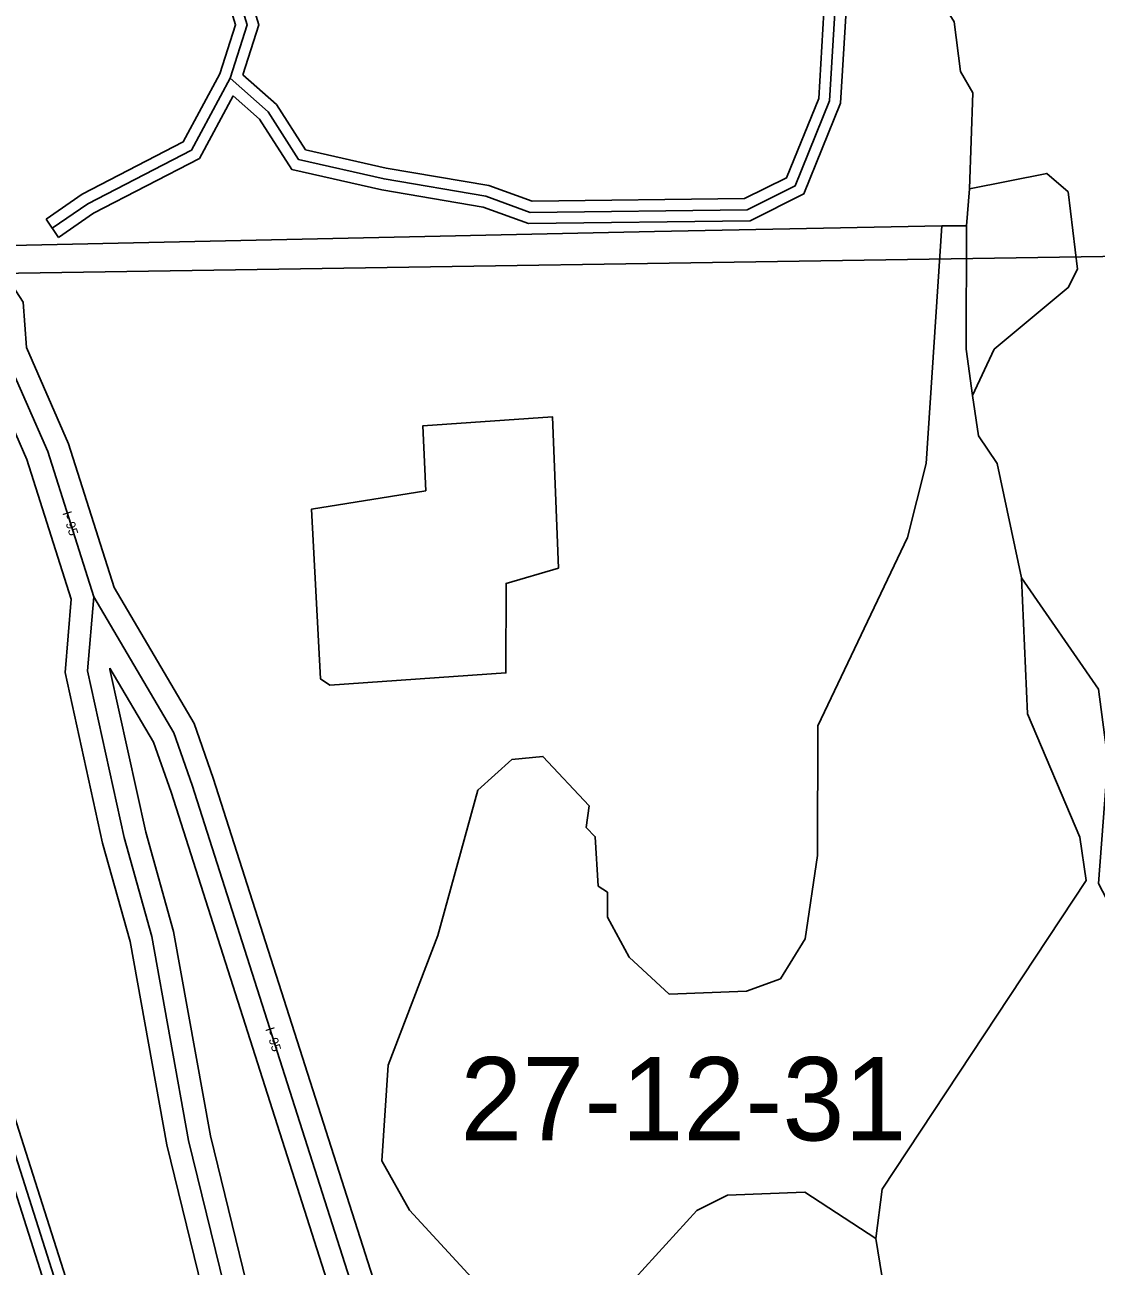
# Model space of a CAD drawing. Extents: x 457167 to 656239, y 1787309 to 1969297.
# Drawn here: x 602179 to 605072, y 1853646 to 1856997 of the extents above; entities that cross this region are included whole.
import ezdxf

# ---------------------------------------------------------------- set-up
doc = ezdxf.new("R2010")
doc.units = 0
for name, color, linetype in [('Level 1', 7, 'Continuous'), ('Level 13', 7, 'Continuous'), ('Level 14', 7, 'Continuous'), ('Level 2', 7, 'Continuous'), ('Level 31', 7, 'Continuous'), ('Level 32', 7, 'Continuous'), ('Level 34', 7, 'Continuous'), ('Level 5', 7, 'Continuous'), ('Level 7', 7, 'Continuous')]:
    doc.layers.add(name, color=color, linetype=linetype)

msp = doc.modelspace()

# ---------------------------------------------------------------- linework, layer by layer
at = {"layer": 'Level 1'}
msp.add_line((601829.454, 1856321.682), (605453.433, 1856377.391), dxfattribs=at)
at = {"layer": 'Level 13'}
for points in [[(602364.771, 1855452.871), (602240.559, 1855845.044), (602124.124, 1856111.754), (602116.017, 1856228.491), (602049.636, 1856328.95)], [(603435.562, 1851606.682), (603226.41, 1852058.606), (603210.01, 1852166.991), (603160.137, 1852242.334), (602778.426, 1853343.222), (602621.136, 1853985.256), (602521.973, 1854535.57), (602447.233, 1854802.582), (602347.93, 1855252.9), (602364.771, 1855452.871)], [(603251.367, 1853042.916), (603120.168, 1853459.458), (603070.344, 1853567.891), (602630.791, 1854944.132), (602581.018, 1855085.656), (602364.771, 1855452.871)]]:
    msp.add_lwpolyline(points, dxfattribs=at)
at = {"layer": 'Level 14'}
for points in [[(602419.92, 1855477.463), (602296.808, 1855866.164), (602183.262, 1856126.256), (602174.78, 1856248.397), (602104.315, 1856355.036)], [(602303.985, 1855446.073), (602184.31, 1855823.924), (602064.985, 1856097.252), (602057.254, 1856208.585), (601994.957, 1856302.861)], [(603308.596, 1853060.941), (603176.263, 1853481.082), (603126.39, 1853589.626), (602687.683, 1854963.217), (602635.683, 1855111.071), (602419.92, 1855477.463)], [(603381.11, 1851581.481), (603168.365, 1852041.17), (603152.667, 1852144.917), (603105.926, 1852215.526), (602720.817, 1853326.219), (602562.416, 1853972.785), (602463.427, 1854522.133), (602389, 1854788.024), (602287.377, 1855248.866), (602303.985, 1855446.073)], [(603490.015, 1851631.882), (603284.456, 1852076.043), (603267.355, 1852189.066), (603214.347, 1852269.141), (602836.036, 1853360.226), (602679.856, 1853997.726), (602580.519, 1854549.007), (602505.465, 1854817.14), (602408.483, 1855256.933), (602408.737, 1855259.966)], [(603194.138, 1853024.891), (603064.072, 1853437.835), (603014.298, 1853546.158), (602573.9, 1854925.048), (602526.354, 1855060.241), (602408.737, 1855259.965)]]:
    msp.add_lwpolyline(points, dxfattribs=at)
at = {"layer": 'Level 31'}
for points in [[(602733.165, 1856852.679), (602779.527, 1856996.973), (602702.537, 1857246.171), (602652.469, 1857401.876), (602675.284, 1857551.659), (602721.405, 1857751.589), (602752.911, 1857968.996)], [(604488.633, 1857314.916), (604391.432, 1857229.598), (604376.762, 1857209.256), (604351.99, 1856791.843), (604259.042, 1856562.522), (604129.719, 1856497.976)], [(602252.94, 1856447.746), (602348.798, 1856513.966), (602628.8, 1856658.651), (602733.165, 1856852.679)], [(604129.719, 1856497.976), (603543.7, 1856490.438), (603423.759, 1856534.243), (603148.805, 1856580.816), (602918.106, 1856633.145), (602835.849, 1856761.987), (602733.165, 1856852.679)], [(601862.03, 1854063.809), (602093.555, 1854131.834), (602486.724, 1852895.785)]]:
    msp.add_lwpolyline(points, dxfattribs=at)
at = {"layer": 'Level 32'}
msp.add_line((602236.066, 1856472.552), (602269.814, 1856422.94), dxfattribs=at)
for points in [[(602705.443, 1856864.471), (602748.074, 1856997.15), (602673.924, 1857237.15), (602621.747, 1857399.415), (602645.795, 1857557.298), (602691.894, 1857757.121), (602717.354, 1857932.812)], [(602767.728, 1856862.177), (602810.98, 1856996.797), (602731.15, 1857255.191), (602683.19, 1857404.339), (602704.771, 1857546.02), (602750.918, 1857746.056), (602781.57, 1857957.589)], [(604462.795, 1857332.156), (604369.086, 1857249.902), (604347.33, 1857219.734), (604322.334, 1856798.542), (604235.498, 1856584.301), (604122.465, 1856527.886)], [(604514.468, 1857297.676), (604413.777, 1857209.294), (604406.193, 1857198.777), (604381.645, 1856785.144), (604282.586, 1856540.743), (604136.97, 1856468.065)], [(602236.066, 1856472.552), (602333.324, 1856539.739), (602606.779, 1856681.041), (602705.443, 1856864.471)], [(604122.465, 1856527.886), (603548.82, 1856520.507), (603431.473, 1856563.365), (603154.633, 1856610.256), (602936.761, 1856659.676), (602858.867, 1856781.684), (602767.728, 1856862.177)], [(602269.814, 1856422.94), (602364.273, 1856488.194), (602650.823, 1856636.261), (602741.663, 1856805.146)], [(604136.97, 1856468.065), (603538.58, 1856460.37), (603416.044, 1856505.122), (603142.978, 1856551.375), (602899.451, 1856606.613), (602812.83, 1856742.291), (602741.663, 1856805.146)], [(601853.574, 1854092.592), (602113.25, 1854168.889), (602514.776, 1852906.564)], [(601898.87, 1854043.363), (602073.86, 1854094.779), (602448.785, 1852916.087)]]:
    msp.add_lwpolyline(points, dxfattribs=at)
at = {"layer": 'Level 5'}
for p, q in [((604721.219, 1856454.528), (604729.648, 1856554.57)), ((604721.219, 1856454.528), (604654.528, 1856454.598)), ((604493.135, 1853620.423), (604476.564, 1853720.485))]:
    msp.add_line(p, q, dxfattribs=at)
for points in [[(604729.648, 1856554.57), (604738.276, 1856812.994), (604705.005, 1856871.375), (604688.455, 1857004.757), (604513.69, 1857288.391), (604280.536, 1857538.743), (603464.043, 1857981.416), (603389.111, 1858056.537), (603389.34, 1858273.281), (603481.23, 1858448.244), (603523.238, 1858756.619), (603525.265, 1860682.308), (603475.602, 1861024.153), (603492.501, 1861215.896), (603559.321, 1861365.849)], [(592916.771, 1856200.319), (603879.218, 1856438.774), (604654.528, 1856454.598)], [(604737.402, 1855996.031), (604720.86, 1856121.083), (604721.219, 1856454.528)], [(604870.257, 1855504.034), (604803.894, 1855812.569), (604753.973, 1855887.63), (604737.402, 1855996.031)], [(604476.564, 1853720.485), (604493.393, 1853853.837), (605044.475, 1854686.912), (605027.893, 1854803.614), (604886.54, 1855137.239), (604870.257, 1855504.034)]]:
    msp.add_lwpolyline(points, dxfattribs=at)
msp.add_lwpolyline([(603002.645, 1855214.251), (602977.635, 1855230.961), (602953.111, 1855689.488), (603261.615, 1855739.181), (603253.444, 1855914.243), (603603.598, 1855938.895), (603619.85, 1855530.379), (603478.1, 1855488.857), (603477.841, 1855247.114), (603002.645, 1855214.251)], close=True, dxfattribs=at)
at = {"layer": 'Level 7'}
for points in [[(604737.402, 1855996.031), (604795.882, 1856121.014), (604996.153, 1856287.507), (605021.193, 1856337.528), (604996.411, 1856545.941), (604938.12, 1856596.021), (604729.648, 1856554.57)], [(603417.721, 1853579.887), (603217.887, 1853796.86), (603142.985, 1853930.301), (603159.924, 1854188.726), (603293.693, 1854538.692), (603402.452, 1854930.398), (603494.253, 1855013.661), (603577.614, 1855021.901), (603702.526, 1854888.389), (603694.126, 1854830.068), (603719.107, 1854805.028), (603727.308, 1854671.606), (603752.288, 1854654.936), (603752.219, 1854588.245), (603810.48, 1854479.813), (603918.752, 1854379.642), (604127.155, 1854387.753), (604218.885, 1854420.995), (604285.675, 1854529.306), (604319.285, 1854754.35), (604319.642, 1855104.476), (604561.942, 1855612.725), (604612.161, 1855812.768), (604654.528, 1856454.598)], [(604550.253, 1852453.306), (604708.545, 1852344.744), (604775.236, 1852369.685), (604808.705, 1852478.027), (604834.074, 1852811.442), (604909.205, 1852903.074), (605192.767, 1853044.497), (605234.547, 1853119.459), (605218.135, 1853369.583), (605193.155, 1853394.623), (605218.324, 1853544.646), (605502.115, 1853902.812), (605519.024, 1854102.846), (605394.141, 1854269.707), (605177.627, 1854486.68), (605077.785, 1854678.542), (605103.153, 1855011.958), (605078.341, 1855203.731), (604870.257, 1855504.034)], [(604476.564, 1853720.485), (604284.96, 1853845.726), (604076.548, 1853837.625), (603993.157, 1853796.044), (603826.236, 1853612.8)]]:
    msp.add_lwpolyline(points, dxfattribs=at)

# ---------------------------------------------------------------- texts
at = {"layer": 'Level 2'}
msp.add_text('27-12-31', height=225, dxfattribs=at).set_placement((603354.775, 1853985.093))
at = {"layer": 'Level 34'}
for rotation, p in [(287.574231, (602279.955, 1855679.263)), (287.712419, (602827.784, 1854286.263))]:
    msp.add_text('I- 95', height=25, rotation=rotation, dxfattribs=at).set_placement(p)

doc.saveas('drawing.dxf')
